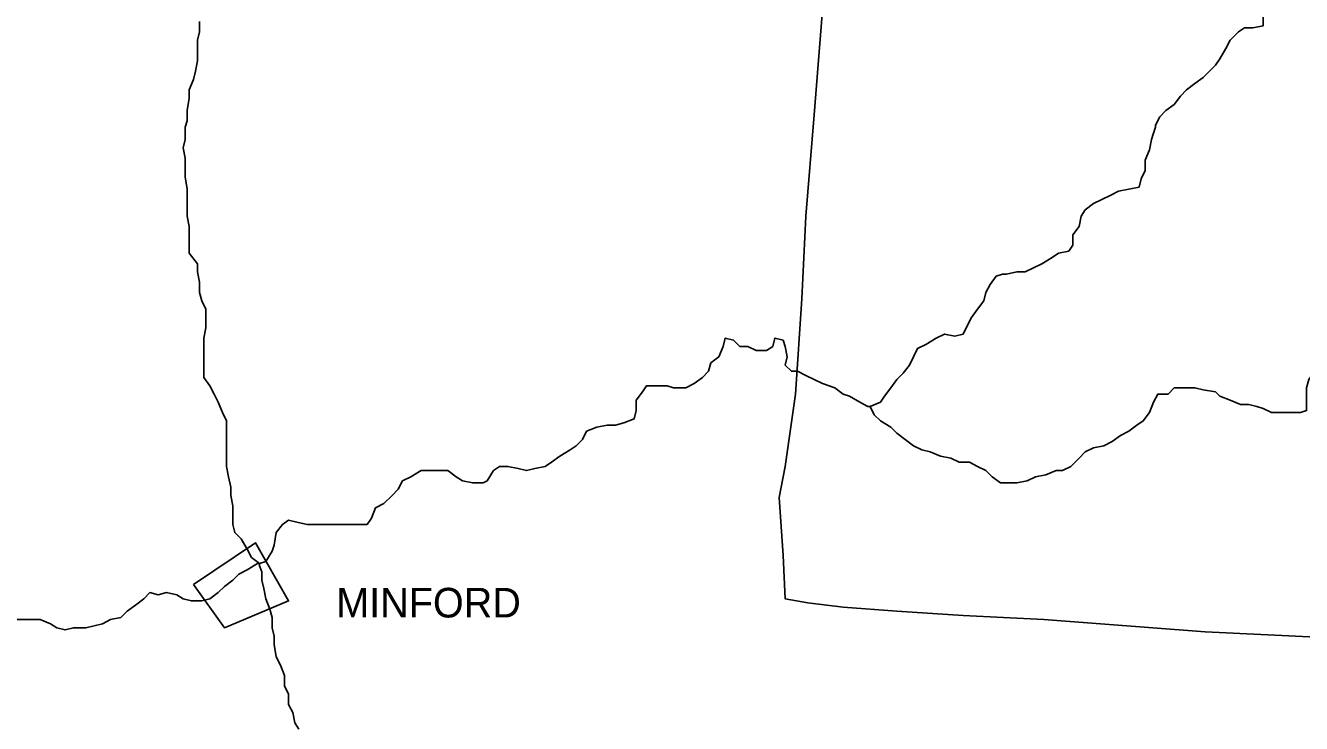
# Model space of a CAD drawing. Extents: x 0 to 34, y 0 to 22.
# Drawn here: x 6.387 to 7.227, y 16.826 to 17.285 of the extents above; entities that cross this region are included whole.
import ezdxf

# ---------------------------------------------------------------- set-up
doc = ezdxf.new("R2010")
doc.units = 0
doc.layers.add('Default', color=7, linetype='Continuous')

msp = doc.modelspace()

# ---------------------------------------------------------------- linework, layer by layer
at = {"layer": 'Default'}
for points in [[(7.2784, 16.8804), (7.16388, 16.88585), (7.05753, 16.89404), (7.00436, 16.89676), (6.96073, 16.89949), (6.92528, 16.90222), (6.9021, 16.90494), (6.8871, 16.90767), (6.88574, 16.9363), (6.88301, 16.97448), (6.88574, 16.98811), (6.8871, 16.99493), (6.89392, 17.04265), (6.89801, 17.10537), (6.90074, 17.1599), (6.90619, 17.22671), (6.91301, 17.31261), (6.80802, 17.32079), (6.72349, 17.32624)], [(6.49307, 17.16536), (6.49307, 17.17217), (6.49307, 17.17763), (6.49171, 17.18581), (6.49171, 17.19262), (6.49171, 17.19808), (6.49035, 17.2049), (6.49171, 17.21035), (6.49171, 17.21853), (6.49307, 17.22262), (6.49307, 17.22944), (6.49444, 17.23762), (6.49444, 17.24307), (6.49716, 17.24989), (6.49853, 17.25534), (6.49989, 17.26216), (6.49989, 17.26761), (6.49989, 17.27579), (6.50125, 17.28125), (6.50125, 17.28806)], [(7.13116, 17.21989), (7.13388, 17.22535), (7.13797, 17.22944), (7.14343, 17.23353), (7.14752, 17.23898), (7.15161, 17.24307), (7.15706, 17.24716), (7.16251, 17.25125), (7.1666, 17.25534), (7.17069, 17.25943), (7.17342, 17.26352), (7.17751, 17.27034), (7.18024, 17.27579), (7.18569, 17.28125), (7.18978, 17.28397), (7.19524, 17.28397), (7.20205, 17.28534), (7.20205, 17.29215)], [(7.03299, 17.12173), (7.03981, 17.12309), (7.04526, 17.12309), (7.05071, 17.12582), (7.05617, 17.12854), (7.06298, 17.13263), (7.06707, 17.13536), (7.07389, 17.13672), (7.07662, 17.14081), (7.07662, 17.14763), (7.08071, 17.15309), (7.08207, 17.1599), (7.0848, 17.16399), (7.09025, 17.16808), (7.09571, 17.17081), (7.10116, 17.17354), (7.10661, 17.17626), (7.11343, 17.17763), (7.12025, 17.17899), (7.12161, 17.18444), (7.12434, 17.1899), (7.12434, 17.19671), (7.12707, 17.20353), (7.12843, 17.21035), (7.12979, 17.21444), (7.13116, 17.21853), (7.13116, 17.21989)], [(6.51898, 17.02492), (6.51625, 17.03038), (6.51353, 17.03719), (6.5108, 17.04265), (6.50807, 17.0481), (6.50398, 17.05356), (6.50398, 17.05901), (6.50398, 17.06583), (6.50398, 17.07264), (6.50398, 17.07946), (6.50535, 17.08628), (6.50535, 17.09173), (6.50535, 17.09855), (6.50262, 17.104), (6.50125, 17.10946), (6.50125, 17.11627), (6.49989, 17.12309), (6.49989, 17.12854), (6.49444, 17.13536), (6.49444, 17.13945), (6.49444, 17.14763), (6.49444, 17.15309), (6.49307, 17.1599), (6.49307, 17.16399), (6.49307, 17.16536)], [(6.943, 17.03447), (6.94982, 17.03719), (6.95255, 17.04128), (6.95664, 17.04674), (6.96073, 17.05219), (6.96482, 17.05628), (6.96891, 17.06174), (6.97164, 17.06719), (6.97436, 17.07264), (6.97982, 17.07537), (6.98663, 17.07946), (6.99209, 17.08219), (6.9989, 17.08082), (7.00436, 17.08219), (7.00708, 17.08764), (7.00981, 17.09309), (7.0139, 17.09855), (7.01799, 17.104), (7.01935, 17.10946), (7.02208, 17.11491), (7.02617, 17.12036), (7.03026, 17.12173), (7.03299, 17.12173)], [(6.72895, 16.99493), (6.73304, 16.99766), (6.73849, 17.00175), (6.74531, 17.00584), (6.7494, 17.00856), (6.75349, 17.01265), (6.75621, 17.01811), (6.76303, 17.02083), (6.76985, 17.0222), (6.7753, 17.0222), (6.78076, 17.02356), (6.78757, 17.02629), (6.78894, 17.03174), (6.78894, 17.03856), (6.79303, 17.04401), (6.79575, 17.0481), (6.80257, 17.0481), (6.80939, 17.0481), (6.81348, 17.04674), (6.82166, 17.04674), (6.82711, 17.04947), (6.83257, 17.05356), (6.83666, 17.05765), (6.83802, 17.0631), (6.84347, 17.06719), (6.8462, 17.07401), (6.84756, 17.07946), (6.85302, 17.0781), (6.85711, 17.07401), (6.86256, 17.07401), (6.86256, 17.07401), (6.86256, 17.07401)], [(6.86256, 17.07401), (6.86802, 17.07128), (6.87483, 17.07128), (6.87892, 17.07401), (6.88029, 17.07946), (6.88574, 17.0781), (6.8871, 17.07401), (6.88847, 17.06719), (6.8871, 17.06174), (6.89119, 17.05765), (6.89528, 17.05765)], [(7.20205, 17.0331), (7.20751, 17.03038), (7.21432, 17.03038), (7.21978, 17.03038), (7.22659, 17.03038), (7.23069, 17.03174), (7.23069, 17.03856), (7.23069, 17.04674), (7.23205, 17.05219), (7.23614, 17.05765), (7.23887, 17.06174), (7.23887, 17.06174)], [(6.89528, 17.05765), (6.90074, 17.05492), (6.90619, 17.05219), (6.91164, 17.04947), (6.91983, 17.04674), (6.92528, 17.04265), (6.92937, 17.04128), (6.93619, 17.03719), (6.94164, 17.03447), (6.943, 17.03447), (6.943, 17.03447)], [(7.07526, 16.99493), (7.08071, 17.00038), (7.0848, 17.00447), (7.09025, 17.0072), (7.09707, 17.00856), (7.10252, 17.01129), (7.10798, 17.01538), (7.11343, 17.01811), (7.11888, 17.0222), (7.12297, 17.02492), (7.12707, 17.03038), (7.12979, 17.03719), (7.13252, 17.04265), (7.13934, 17.04265), (7.14343, 17.04674), (7.14343, 17.04674)], [(7.14343, 17.04674), (7.14888, 17.04674), (7.15706, 17.04674), (7.16251, 17.04537), (7.17069, 17.04401), (7.17342, 17.04128), (7.18024, 17.03856), (7.18706, 17.03583), (7.19251, 17.03583), (7.19796, 17.03447), (7.20205, 17.0331), (7.20205, 17.0331)], [(6.943, 17.03447), (6.94573, 17.02901), (6.94982, 17.02492), (6.95664, 17.02083), (6.96073, 17.01674), (6.96618, 17.01265), (6.97164, 17.00856), (6.97709, 17.00584), (6.98254, 17.00447), (6.98936, 17.00175), (6.99618, 17.00038), (7.00163, 16.99766), (7.00845, 16.99766), (7.0139, 16.99493), (7.01935, 16.9922), (7.02345, 16.98811), (7.0289, 16.98402), (7.03435, 16.98402), (7.03981, 16.98402), (7.04662, 16.98538), (7.05208, 16.98811), (7.05889, 16.98947), (7.06571, 16.9922), (7.0698, 16.9922), (7.07526, 16.99493), (7.07526, 16.99493)], [(6.54079, 16.93085), (6.53534, 16.93494), (6.53261, 16.94039), (6.52852, 16.94721), (6.52443, 16.9513), (6.52307, 16.95675), (6.52307, 16.96357), (6.52307, 16.96902), (6.52171, 16.97584), (6.52171, 16.98129), (6.52034, 16.98811), (6.51898, 16.99493), (6.51898, 17.00175), (6.51898, 17.00856), (6.51898, 17.01402), (6.51898, 17.02083), (6.51898, 17.02492)], [(6.61169, 16.95675), (6.61442, 16.96084), (6.61715, 16.96766), (6.6226, 16.97039), (6.62805, 16.97584), (6.63214, 16.97993), (6.63487, 16.98538), (6.64032, 16.98811), (6.64714, 16.9922), (6.65259, 16.9922), (6.65805, 16.9922), (6.66487, 16.9922), (6.67032, 16.98811), (6.67441, 16.98538), (6.68123, 16.98402), (6.68804, 16.98402), (6.69077, 16.98538), (6.69486, 16.9922), (6.69895, 16.99493), (6.7044, 16.99493), (6.71122, 16.99356), (6.71668, 16.9922), (6.72213, 16.99356), (6.72895, 16.99493)], [(6.54079, 16.93085), (6.54488, 16.93221), (6.54897, 16.93903), (6.55034, 16.94312), (6.5517, 16.9513), (6.55579, 16.95675), (6.55988, 16.95948), (6.56534, 16.95812), (6.57215, 16.95675), (6.57761, 16.95675), (6.58442, 16.95675), (6.59124, 16.95675), (6.59806, 16.95675), (6.60487, 16.95675), (6.61033, 16.95675), (6.61169, 16.95675)], [(6.49716, 16.91721), (6.53807, 16.94448), (6.55988, 16.90631), (6.51762, 16.88858), (6.49716, 16.91721)], [(6.41263, 16.88722), (6.41809, 16.88858), (6.42627, 16.88858), (6.43172, 16.88994), (6.43717, 16.89131), (6.44263, 16.89404), (6.44944, 16.8954), (6.45354, 16.89949), (6.45899, 16.90358), (6.46444, 16.90767), (6.46853, 16.91176), (6.47399, 16.9104), (6.47944, 16.91176), (6.48626, 16.9104), (6.49035, 16.90767), (6.4958, 16.90631), (6.50262, 16.90631), (6.50807, 16.90767), (6.51353, 16.91176), (6.51762, 16.91585), (6.52307, 16.91994), (6.52716, 16.92403), (6.53261, 16.92676), (6.53943, 16.93085), (6.54079, 16.93085)], [(6.5667, 16.82177), (6.56397, 16.82586), (6.56261, 16.83268), (6.55988, 16.83813), (6.55988, 16.84495), (6.55716, 16.85041), (6.55716, 16.85722), (6.55443, 16.86404), (6.5517, 16.86949), (6.55034, 16.87767), (6.55034, 16.88313), (6.54897, 16.88858), (6.54897, 16.8954), (6.54761, 16.90085), (6.54488, 16.90767), (6.54352, 16.91449), (6.54216, 16.91994), (6.54216, 16.92539), (6.54079, 16.92948), (6.54079, 16.93085)], [(6.33628, 16.83677), (6.33628, 16.84223), (6.33901, 16.85041), (6.33901, 16.85722), (6.34173, 16.86131), (6.3431, 16.86813), (6.34582, 16.87358), (6.34719, 16.87904), (6.35128, 16.88449), (6.35401, 16.88994), (6.35946, 16.89131), (6.36628, 16.89267), (6.37173, 16.89404), (6.37855, 16.89404), (6.38536, 16.89404), (6.39082, 16.89404), (6.39627, 16.89404), (6.40309, 16.89131), (6.40718, 16.88858), (6.41263, 16.88722), (6.41263, 16.88722)]]:
    msp.add_lwpolyline(points, dxfattribs=at)

# ---------------------------------------------------------------- texts
msp.add_text('MINFORD', height=0.019502, dxfattribs=at).set_placement((6.59124, 16.8954))

doc.saveas('drawing.dxf')
